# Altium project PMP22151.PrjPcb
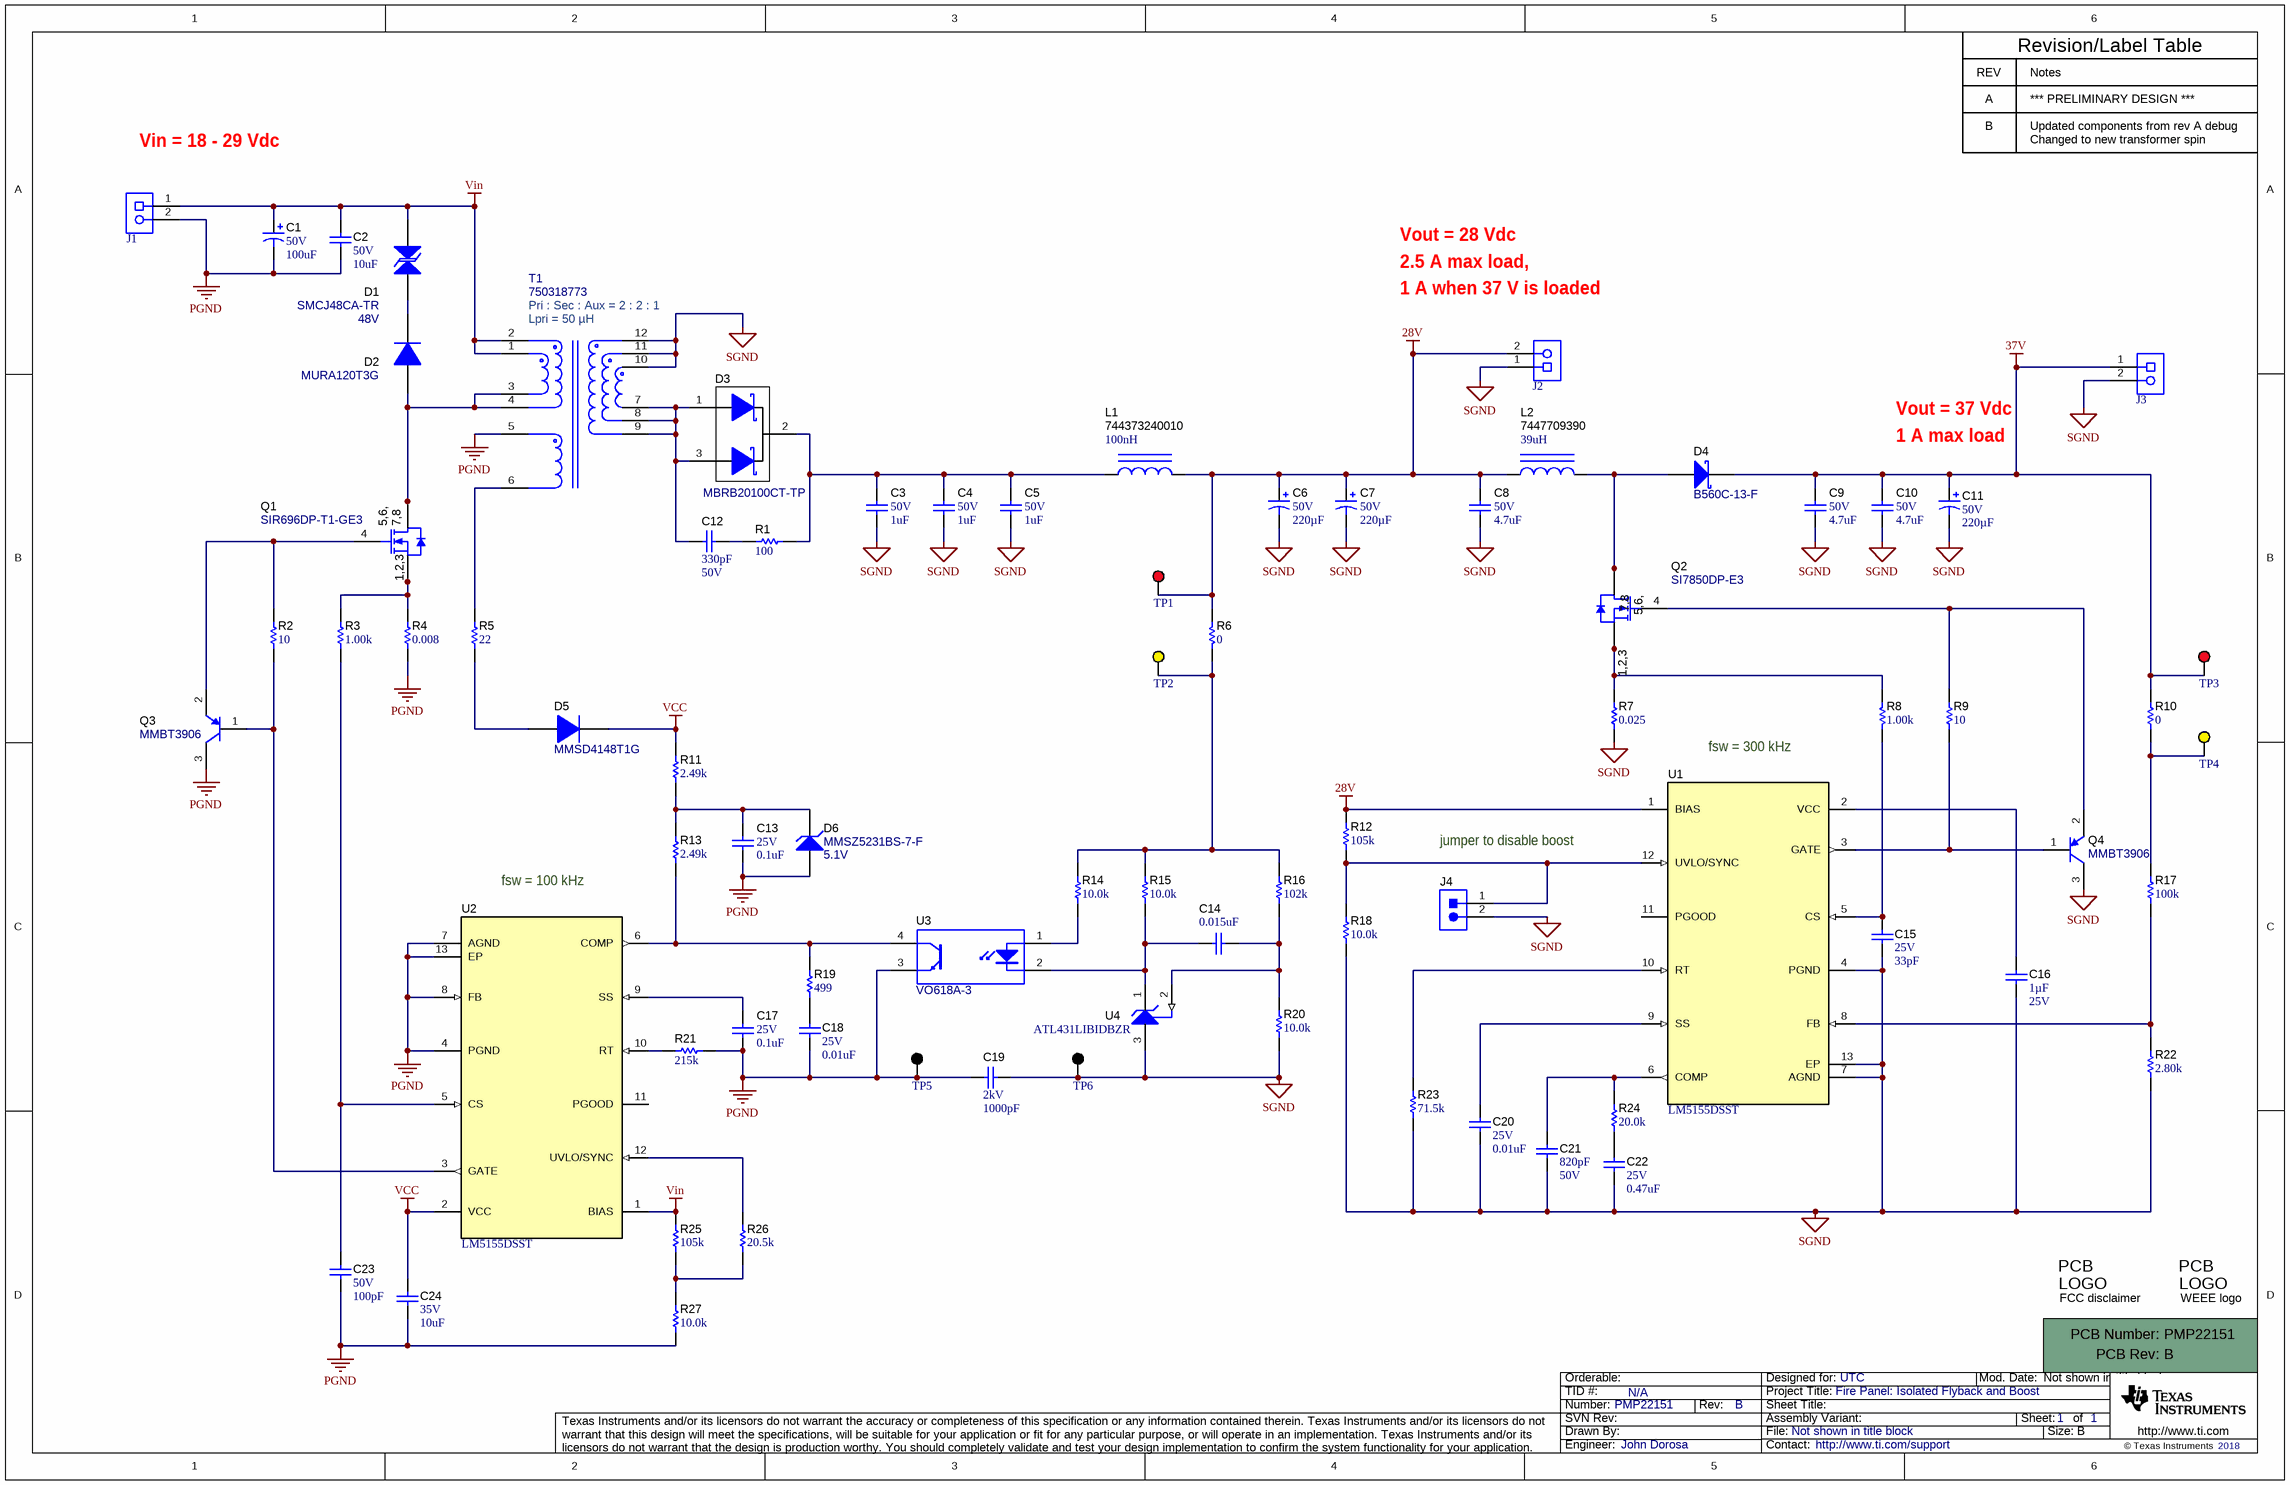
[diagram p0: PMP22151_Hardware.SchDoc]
TID: N/A; TechSupport: http://www.ti.com/support; SCH_Rev: B; PRJ_Title: Fire Panel: Isolated Flyback and Boost; PRJ_Number: PMP22151; PRJ_Engineer: John Dorosa; PRJ_Customer: UTC; PCB_Rev: B; PCB_Layout: John Dorosa; CopyrightYear: 2018
1 sheet, 81 parts. Net scope: global (net labels, ports and power ports of the same name join across sheets).
Board file: PMP22151_PCB.PcbDoc

## Sheet PMP22151_Hardware.SchDoc
size 431 x 279 mm; Date: Not shown in title block; ApprovedBy: Not shown in title block; CheckedBy: Not shown in title block; Author: Not shown in title block; CompanyName: Not shown in title block; Engineer: Not shown in title block; Organization: Not shown in title block; Address1: Not shown in title block; Address2: Not shown in title block; Address3: Not shown in title block; Address4: Not shown in title block; DocumentNumber: 1; Revision: Use project parameter SCH_Rev; SheetNumber: 1; SheetTotal: 1; PageSetup: Record=PageOptions¦CenterHorizontal=True¦CenterVertical=True¦PrintScale=1.00¦XCorrection=1.00¦YCorrection=1.00¦PrintKind=0¦BorderSize=5000000¦LeftOffset=0¦BottomOffset=0¦Orientation=2¦PaperLength=1000¦PaperWidth=1000¦Scale=100¦PaperSource=15¦PrintQuality=600¦MediaType=1¦DitherType=10¦PaperKind=Letter¦PrintScaleMode=1

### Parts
!PCB1  Printed Circuit Board  (value not drawn)  (mechanical)
C1  VDC_V: 50V  ValueDisplayed: 100uF  [ZLJ_800X1150]  (hidden comment: 50ZLJ100MT78X11.5)
C2  VDC_V: 50V  ValueDisplayed: 10uF  [1206_180]  (hidden comment: GRM31CR61H106KA12L)
C3  VDC_V: 50V  ValueDisplayed: 1uF  [1206]  (hidden comment: GRM31MR71H105KA88L)
C4  VDC_V: 50V  ValueDisplayed: 1uF  [1206]  (hidden comment: GRM31MR71H105KA88L)
C5  VDC_V: 50V  ValueDisplayed: 1uF  [1206]  (hidden comment: GRM31MR71H105KA88L)
C6  VDC_V: 50V  ValueDisplayed: 220µF  [WCAP-ATLI_1000x1600]  (hidden comment: 860080675015)
C7  VDC_V: 50V  ValueDisplayed: 220µF  [WCAP-ATLI_1000x1600]  (hidden comment: 860080675015)
C8  VDC_V: 50V  ValueDisplayed: 4.7uF  [1206_180]  (hidden comment: GRM31CR71H475KA12L)
C9  VDC_V: 50V  ValueDisplayed: 4.7uF  [1206_180]  (hidden comment: GRM31CR71H475KA12L)
C10  VDC_V: 50V  ValueDisplayed: 4.7uF  [1206_180]  (hidden comment: GRM31CR71H475KA12L)
C11  VDC_V: 50V  ValueDisplayed: 220µF  [WCAP-ATLI_1000x1600]  (hidden comment: 860080675015)
C12  Cap_F: 330pF  VDC_V: 50V  [0603]  (hidden comment: GRM188R71H331KA01D)
C13  VDC_V: 25V  ValueDisplayed: 0.1uF  [0603]  (hidden comment: GRM188R71E104KA01D)
C14  ValueDisplayed: 0.015uF  [0603]  (hidden comment: GRM188R71E153KA01D)
C15  VDC_V: 25V  ValueDisplayed: 33pF  [0402]  (hidden comment: GRM1555C1E330JA01D)
C16  Cap_F: 1µF  VDC_V: 25V  [0805_HV]  (hidden comment: GRM219R71E105KA88D)
C17  VDC_V: 25V  ValueDisplayed: 0.1uF  [0603]  (hidden comment: GRM188R71E104KA01D)
C18  VDC_V: 25V  ValueDisplayed: 0.01uF  [0603]  (hidden comment: GRM188R71E103KA01D)
C19  VDC_V: 2kV  ValueDisplayed: 1000pF  [1812_254]  (hidden comment: 1812GC102KA1)
C20  VDC_V: 25V  ValueDisplayed: 0.01uF  [0603]  (hidden comment: GRM188R71E103KA01D)
C21  Cap_F: 820pF  VDC_V: 50V  [0603]  (hidden comment: GRM188R71H821KA01D)
C22  VDC_V: 25V  ValueDisplayed: 0.47uF  [0603]  (hidden comment: GCM188R71E474KA64D)
C23  VDC_V: 50V  ValueDisplayed: 100pF  [0402]  (hidden comment: 885012205055)
C24  VDC_V: 35V  ValueDisplayed: 10uF  [1206_190]  (hidden comment: C3216X7R1V106M160AC)
D1  SMCJ48CA-TR  value 48V  [SMC_Bi]
D2  MURA120T3G  [SMA]
D3  MBRB20100CT-TP  [DDPAK]
D4  B560C-13-F  [SMC]
D5  MMSD4148T1G  [SOD-123]
D6  MMSZ5231BS-7-F  value 5.1V  [SOD-323]
J1  691214110002  [Wurth_691214110002]  (value not drawn)
J2  691214110002  [Wurth_691214110002]  (value not drawn)
J3  691214110002  [Wurth_691214110002]  (value not drawn)
J4  61300211121  [WURTH_61300211121]  (value not drawn)
L1  744373240010  ValueDisplayed: 100nH  [WE-LHMI_4020]
L2  7447709390  ValueDisplayed: 39uH  [WE-PD_1210]
Logo1  FCC disclaimer  [FCC_disclaimer]  (no BOM)
Logo2  WEEE logo  [WEEE_Minimum]  (no BOM)
Q1  SIR696DP-T1-GE3  [PowerPAK_SO-8]
Q2  SI7850DP-E3  [PowerPAK_SO-8]
Q3  MMBT3906  [SOT-23]
Q4  MMBT3906  [SOT-23]
R1  ValueDisplayed: 100  [2512]  (hidden comment: CRCW2512100RJNEG)
R2  ValueDisplayed: 10  [0603]  (hidden comment: CRCW060310R0JNEA)
R3  ValueDisplayed: 1.00k  [0603]  (hidden comment: CRCW06031K00FKEA)
R4  ValueDisplayed: 0.008  [2512]  (hidden comment: ERJ-M1WSF8M0U)
R5  ValueDisplayed: 22  [0603]  (hidden comment: CRCW060322R0JNEA)
R6  ValueDisplayed: 0  [0603]  (hidden comment: CRCW06030000Z0EA)
R7  ValueDisplayed: 0.025  [2010]  (hidden comment: CSRN2010FK25L0)
R8  ValueDisplayed: 1.00k  [0603]  (hidden comment: CRCW06031K00FKEA)
R9  ValueDisplayed: 10  [0603]  (hidden comment: CRCW060310R0JNEA)
R10  ValueDisplayed: 0  [0603]  (hidden comment: CRCW06030000Z0EA)
R11  ValueDisplayed: 2.49k  [0603]  (hidden comment: CRCW06032K49FKEA)
R12  ValueDisplayed: 105k  [0603]  (hidden comment: CRCW0603105KFKEA)
R13  ValueDisplayed: 2.49k  [0603]  (hidden comment: CRCW06032K49FKEA)
R14  ValueDisplayed: 10.0k  [0603]  (hidden comment: CRCW060310K0FKEA)
R15  ValueDisplayed: 10.0k  [0603]  (hidden comment: CRCW060310K0FKEA)
R16  ValueDisplayed: 102k  [0603]  (hidden comment: CRCW0603102KFKEA)
R17  ValueDisplayed: 100k  [0603]  (hidden comment: CRCW0603100KFKEA)
R18  ValueDisplayed: 10.0k  [0603]  (hidden comment: CRCW060310K0FKEA)
R19  ValueDisplayed: 499  [0603]  (hidden comment: CRCW0603499RFKEA)
R20  ValueDisplayed: 10.0k  [0603]  (hidden comment: CRCW060310K0FKEA)
R21  ValueDisplayed: 215k  [0603]  (hidden comment: CRCW0603215KFKEA)
R22  ValueDisplayed: 2.80k  [0603]  (hidden comment: CRCW06032K80FKEA)
R23  ValueDisplayed: 71.5k  [0603]  (hidden comment: CRCW060371K5FKEA)
R24  ValueDisplayed: 20.0k  [0603]  (hidden comment: CRCW060320K0FKEA)
R25  ValueDisplayed: 105k  [0603]  (hidden comment: CRCW0603105KFKEA)
R26  ValueDisplayed: 20.5k  [0603]  (hidden comment: CRCW060320K5FKEA)
R27  ValueDisplayed: 10.0k  [0603]  (hidden comment: CRCW060310K0FKEA)
T1  750318773  [FP-750318773_PTH_32MM0_33MM0-MFG]
TP1  5000  [Keystone5000]  (value not drawn)
TP2  5004  [Keystone5004]  (value not drawn)
TP3  5000  [Keystone5000]  (value not drawn)
TP4  5004  [Keystone5004]  (value not drawn)
TP5  5011  [Keystone5011]  (value not drawn)
TP6  5011  [Keystone5011]  (value not drawn)
U1  LM5155DSST  [DSS0012B]
U2  LM5155DSST  [DSS0012B]
U3  VO618A-3  [DIP-4]
U4  ATL431LIBIDBZR  [DBZ0003A_N]

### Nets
28V: C6.1(+) C7.1(+) C8.1 J2.2 L1.2 L2.1 R6.2 R12.2 TP1.1 U1.1(BIAS)
37V: C9.1 C10.1 C11.1(+) D4.1(K) J3.1 R10.2 TP3.1
PGND: C1.2(-) C2.2 C13.1 C17.1 C18.1 C19.2 C23.2 C24.2 D6.2(A) J1.2 Q3.3(C) R4.1 R21.2 R27.1 T1.5 TP5.1 U2.4(PGND) U2.7(AGND) U2.8(FB) U2.13(EP) U3.3(E)
SGND: C3.2 C4.2 C5.2 C6.2(-) C7.2(-) C8.2 C9.2 C10.2 C11.2(-) C15.2 C16.2 C19.1 C20.2 C21.2 C22.2 J2.1 J3.2 J4.2 Q4.3(C) R7.1 R18.1 R20.1 R22.1 R23.1 T1.10 T1.11 T1.12 TP6.1 U1.4(PGND) U1.7(AGND) U1.13(EP) U4.3(ANODE)
VCC: C24.1 D5.1(K) R11.2 U2.2(VCC)
Vin: C1.1(+) C2.1 D1.1 J1.1 R25.2 T1.1 T1.2 U2.1(BIAS)
NetC3_1: C3.1 C4.1 C5.1 D3.2(K) L1.1 R1.2
NetC12_1: C12.1 R1.1
NetC12_2: C12.2 D3.1(A) D3.3(A) T1.7 T1.8 T1.9
NetC13_2: C13.2 D6.1(K) R11.1 R13.2
NetC14_1: C14.1 R16.1 R20.2 U4.2(REF)
NetC14_2: C14.2 R15.1 U3.2(K) U4.1(CATHODE)
NetC15_1: C15.1 R8.1 U1.5(CS)
NetC16_1: C16.1 U1.2(VCC)
NetC17_2: C17.2 U2.9(SS)
NetC18_2: C18.2 R19.1
NetC20_1: C20.1 U1.9(SS)
NetC21_1: C21.1 R24.2 U1.6(COMP)
NetC22_1: C22.1 R24.1
NetC23_1: C23.1 R3.1 U2.5(CS)
NetD1_2: D1.2 D2.1(K)
NetD2_2: D2.2(A) Q1.5(D) Q1.6(D) Q1.7(D) Q1.8(D) Q1.9(D) T1.3 T1.4
NetD4_2: D4.2(A) L2.2 Q2.5(D) Q2.6(D) Q2.7(D) Q2.8(D) Q2.9(D)
NetD5_2: D5.2(A) R5.1
NetJ4_1: J4.1 R12.1 R18.2 U1.12(UVLO/SYNC)
NetQ1_1: Q1.1(S) Q1.2(S) Q1.3(S) R3.2 R4.2
NetQ1_4: Q1.4(G) Q3.2(E) R2.2
NetQ2_1: Q2.1(S) Q2.2(S) Q2.3(S) R7.2 R8.2
NetQ2_4: Q2.4(G) Q4.2(E) R9.2
NetQ3_1: Q3.1(B) R2.1 U2.3(GATE)
NetQ4_1: Q4.1(B) R9.1 U1.3(GATE)
NetR5_2: R5.2 T1.6
NetR6_1: R6.1 R14.2 R15.2 R16.2 TP2.1
NetR10_1: R10.1 R17.2 TP4.1
NetR13_1: R13.1 R19.2 U2.6(COMP) U3.4(C)
NetR14_1: R14.1 U3.1(A)
NetR17_1: R17.1 R22.2 U1.8(FB)
NetR21_1: R21.1 U2.10(RT)
NetR23_2: R23.2 U1.10(RT)
NetR25_1: R25.1 R26.1 R27.2
NetR26_2: R26.2 U2.12(UVLO/SYNC)

Not connected (* = marked no-connect by the designer): U1 11(PGOOD); U2 11(PGOOD)

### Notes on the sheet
- REV
- A
- Notes
- *** PRELIMINARY DESIGN ***
- Revision/Label Table
- Vin = 18 - 29 Vdc
- B
- Updated components from rev A debug
- Changed to new transformer spin
- Vout = 28 Vdc
- 2.5 A max load,
- 1 A when 37 V is loaded
- (near T1) Pri : Sec : Aux = 2 : 2 : 1
- (near T1) Lpri = 50 µH
- Vout = 37 Vdc
- 1 A max load
- fsw = 300 kHz
- fsw = 100 kHz
- jumper to disable boost

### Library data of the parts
!PCB1 = CMP-0003618-2: Manufacturer: Any; PartNumber: PMP22151
C1 = CMP-0009787-2: CAP, AL, 100 uF, 50 V, +/- 20%, 0.12 ohm, TH; Manufacturer: Rubycon; TaMin_C: -40°C; ESR_ohm: 0.12; Polarized: Y; SizeAreaWB_mm2: 100; U/M: EA; Value: 100uF; TaMax_C: 105°C; SizeZ_mm: 13; SizeX_mm: 8; Cap_Case: 8x11.5; SizeArea_mm2: 64; CompType: Capacitor; AEC Qualified: N; Cap_F: 100µF; IRMS_A: 950mA; AEC Category: Q200
C2 = CMP-0008954-2: CAP, CERM, 10 uF, 50 V, +/- 10%, X5R, 1206; Manufacturer: MuRata; TaMin_C: -55°C; Polarized: N; SizeAreaWB_mm2: 10.92; Value1: Unknown; U/M: EA; Value: 10uF; TaMax_C: 85°C; SizeZ_mm: 1.8; SizeX_mm: 3.2; SizeY_mm: 1.6; Cap_Case: 1206; SizeArea_mm2: 5.12; Cap_F: 10µF; AEC Category: Q200
C3-C5 = CMP-0008992-2: CAP, CERM, 1 uF, 50 V, +/- 10%, X7R, 1206; Manufacturer: MuRata; TaMin_C: -55°C; Polarized: N; SizeAreaWB_mm2: 10.92; Value1: Unknown; U/M: EA; Value: 1uF; TaMax_C: 125°C; SizeZ_mm: 1.35; SizeX_mm: 3.2; SizeY_mm: 1.6; SizeArea_mm2: 5.12; Cap_F: 1µF; AEC Category: Q200
C6 C7 C11 = CMP-0081643-1: CAP, AL, 220 µF, 50 V, +/- 20%, TH; Manufacturer: Wurth Elektronik; IRMS_A: 1.385A; SizeAreaWB_mm2: 144; SizeArea_mm2: 100; AEC Qualified: N; AEC Category: Q200; Value: 220uF; TaMax_C: 105°C; SizeZ_mm: 17.5; Polarized: Y; TaMin_C: -55°C; SizeY_mm: 10; U/M: EA; CompType: Capacitor; Cap_Case: 10x16mm
C8-C10 = CMP-0008969-2: CAP, CERM, 4.7 uF, 50 V, +/- 10%, X7R, 1206; Manufacturer: MuRata; TaMin_C: -55°C; Polarized: N; SizeAreaWB_mm2: 10.92; Value1: Unknown; U/M: EA; Value: 4.7uF; TaMax_C: 125°C; SizeZ_mm: 1.8; SizeX_mm: 3.2; SizeY_mm: 1.6; Cap_Case: 2220; SizeArea_mm2: 5.12; Cap_F: 4.7µF; AEC Category: Q200
C12 = CMP-0007449-4: CAP, CERM, 330 pF, 50 V, +/- 10%, X7R, 0603; Manufacturer: MuRata; TaMin_C: -55°C; Polarized: N; SizeAreaWB_mm2: 4.68; Value1: Unknown; U/M: EA; Value: 330pF; TaMax_C: 125°C; SizeZ_mm: 1; SizeX_mm: 1.6; SizeY_mm: 0.8; SizeArea_mm2: 1.28; AEC Category: Q200
C13 C17 = CMP-0007404-4: CAP, CERM, 0.1 uF, 25 V, +/- 10%, X7R, 0603; Manufacturer: MuRata; TaMin_C: -55°C; Polarized: N; SizeAreaWB_mm2: 4.68; Value1: Unknown; U/M: EA; Value: 0.1uF; TaMax_C: 125°C; SizeZ_mm: 1; SizeX_mm: 1.6; SizeY_mm: 0.8; SizeArea_mm2: 1.28; Cap_F: 100nF; AEC Category: Q200
C14 = CMP-0007410-5: CAP, CERM, 0.015 uF, 25 V, +/- 10%, X7R, 0603; Manufacturer: MuRata; TaMin_C: -55°C; Polarized: N; SizeAreaWB_mm2: 4.68; Value1: Unknown; U/M: EA; TaMax_C: 125°C; SizeZ_mm: 1; SizeX_mm: 1.6; SizeY_mm: 0.8; Value2: 25V; SizeArea_mm2: 1.28; Cap_F: 15nF; AEC Category: Q200
C15 = CMP-0006377-2: CAP, CERM, 33 pF, 25 V, +/- 5%, C0G/NP0, 0402; Manufacturer: MuRata; TaMin_C: -55°C; Polarized: N; SizeAreaWB_mm2: 3; Value1: Unknown; U/M: EA; Value: 33pF; TaMax_C: 125°C; SizeZ_mm: 0.6; SizeX_mm: 1; SizeY_mm: 0.5; AEC Category: Q200
C16 = CMP-0008217-2: CAP, CERM, 1 uF, 25 V, +/- 10%, X7R, 0805; Manufacturer: MuRata; TaMin_C: -55°C; Polarized: N; SizeAreaWB_mm2: 6.75; Value1: Unknown; U/M: EA; Value: 1uF; TaMax_C: 125°C; SizeZ_mm: 1.45; SizeX_mm: 2; SizeY_mm: 1.25; Cap_Case: 0805; SizeArea_mm2: 2.5; AEC Category: Q200
C18 C20 = CMP-0007403-4: CAP, CERM, 0.01 uF, 25 V, +/- 10%, X7R, 0603; Manufacturer: MuRata; TaMin_C: -55°C; Polarized: N; SizeAreaWB_mm2: 4.68; Value1: Unknown; U/M: EA; Value: 0.01uF; TaMax_C: 125°C; SizeZ_mm: 1; SizeX_mm: 1.6; SizeY_mm: 0.8; SizeArea_mm2: 1.28; Cap_F: 10nF; AEC Category: Q200
C19 = CMP-0009293-2: CAP, CERM, 1000 pF, 2000 V, +/- 10%, X7R, 1812; Manufacturer: AVX; TaMin_C: -55°C; Polarized: N; SizeAreaWB_mm2: 23.1; Value1: Unknown; U/M: EA; Value: 1000pF; TaMax_C: 125°C; SizeZ_mm: 2.54; SizeX_mm: 4.5; SizeY_mm: 3.2; Cap_Case: 1812; Value2: 2000V; SizeArea_mm2: 14.4; Cap_F: 1nF; AEC Category: Q200
C21 = CMP-0007464-4: CAP, CERM, 820 pF, 50 V, +/- 10%, X7R, 0603; Manufacturer: MuRata; TaMin_C: -55°C; Polarized: N; SizeAreaWB_mm2: 4.68; Value1: Unknown; U/M: EA; Value: 820pF; TaMax_C: 125°C; SizeZ_mm: 1; SizeX_mm: 1.6; SizeY_mm: 0.8; SizeArea_mm2: 1.28; AEC Category: Q200
C22 = CMP-0007142-4: CAP, CERM, 0.47 uF, 25 V, +/- 10%, X7R, AEC-Q200 Grade 1, 0603; Manufacturer: MuRata; TaMin_C: -55°C; Polarized: N; SizeAreaWB_mm2: 4.68; Value1: Unknown; U/M: EA; Value: 0.47uF; TaMax_C: 125°C; SizeZ_mm: 1; SizeX_mm: 1.6; SizeY_mm: 0.8; SizeArea_mm2: 1.28; AEC Qualified: Y; Cap_F: 470nF; AEC Category: Q200
C23 = CMP-0006230-2: CAP, CERM, 100 pF, 50 V, +/- 10%, X7R, 0402; Manufacturer: Wurth Elektronik; TaMin_C: -55°C; Polarized: N; SizeAreaWB_mm2: 3; Value1: Unknown; U/M: EA; Value: 100pF; TaMax_C: 125°C; SizeZ_mm: 0.6; SizeX_mm: 1; SizeY_mm: 0.5; AEC Category: Q200
C24 = CMP-0008706-2: CAP, CERM, 10 uF, 35 V, +/- 20%, X7R, 1206_190; Manufacturer: TDK; TaMin_C: -55°C; Polarized: N; SizeAreaWB_mm2: 10.92; Value1: Unknown; U/M: EA; Value: 10uF; TaMax_C: 125°C; SizeZ_mm: 1.9; SizeX_mm: 3.2; SizeY_mm: 1.6; Cap_Case: 1206; SizeArea_mm2: 5.12; Cap_F: 10µF; AEC Category: Q200
D1 = CMP-0085460-1: Diode, TVS, Bi, 48 V, 77.4 Vc, 1500 W, 20 A, SMC (No Polarity Mark); Manufacturer: STMicroelectronics; AEC Category: Q101; Ipp: 20A; Vc: 77.4V; RJA_CperW: 90; SizeX_mm: 7.94; SizeY_mm: 5.9; SizeArea_mm2: 46.846; SizeAreaWB_mm2: 78.526; Ppk: 1.5kW; AEC Qualified: N; Vbr_Min: 53.3V; SizeZ_mm: 2.62
D2 = CMP-0029038-2: Diode, Ultrafast, 200 V, 1 A, SMA; Manufacturer: ON Semiconductor; Value: 200V; Value1: 1A; Value2: 0.0875V; Vf_V: 87.5mV; SizeY_mm: 2.92; Green_REACh: Passed; SizeX_mm: 5.59; Green_Lifecycle: Active; TJmax_C: 175°C; SizeArea_mm2: 16.3228; SizeAreaWB_mm2: 37.3428; SizeZ_mm: 2.87; AEC Category: Q101
D3 = CMP-0076915-3: Diode, Schottky, 100 V, 20 A, DDPAK; Manufacturer: Micro Commercial Components; Value: 100V; RJC_CperW: 2.0; Io_A: 20A; SizeY_mm: 10.16; Green_REACh: Incomplete; TJmax_C: 150°C; AEC Category: Q101; Vf_V: 850mV; SizeZ_mm: 4.445; Green_Lifecycle: Not Set; SizeX_mm: 15.245; SizeAreaWB_mm2: 209.6992; Value2: 0.85V; SizeArea_mm2: 154.8892
D4 = CMP-0028433-2: Diode, Schottky, 60 V, 5 A, SMC; Manufacturer: Diodes Inc.; Vf_V: 700mV; AEC Category: Q101; Vr_V: 60V; Value1: 5A; RJC_CperW: 10; Value2: 0.7V; Value: 60V; SizeX_mm: 8.13; TJmax_C: 125°C; SizeArea_mm2: 50.5686; Green_REACh: Passed; Green_Lifecycle: Active; SizeAreaWB_mm2: 83.2686; SizeY_mm: 6.22; SizeZ_mm: 2.6
D5 = CMP-0029032-2: Diode, Switching, 100 V, 0.2 A, SOD-123; Manufacturer: ON Semiconductor; Value: 100V; SizeY_mm: 1.7; Io_A: 200mA; SizeAreaWB_mm2: 13.095; SizeArea_mm2: 6.545; Vf_V: 1V; TJmax_C: 150°C; SizeX_mm: 3.85; SizeZ_mm: 1.35; Value1: 0.2A; Green_Lifecycle: Active; AEC Category: Q101; Green_REACh: Passed
D6 = CMP-0005854-3: Diode, Zener, 5.1 V, 200 mW, SOD-323; Manufacturer: Diodes Inc.; SizeX_mm: 2.7; SizeZ_mm: 1; RJA_CperW: 350; Power_W: 200mW; SizeAreaWB_mm2: 8.695; AEC Category: Q101; Value1: 0.2W; SizeArea_mm2: 3.645; SizeY_mm: 1.35
J1-J3 = CMP-0054825-2: Terminal Block, 3.5mm, 2x1, Tin, TH; Manufacturer: Wurth Elektronik; Pitch_mm: 3.5; CT: TRUE; CNHeader: FALSE; Voltage_V: 300V; Gender: Female; Cert_UL: Y; Row_Count: 1; Current_A: 10A
J4 = CMP-0054794-1: Header, 2.54 mm, 2x1, Gold, TH; Manufacturer: Wurth Elektronik; CNHeader: TRUE; Green_Lifecycle: Active; Green_REACh: Passed; CT: FALSE
L1 = CMP-0064065-1: Inductor, Shielded Drum Core, Powdered Iron, 100 nH, 12 A, 0.0032 ohm, SMD; Manufacturer: Wurth Elektronik; Isat: 30A @ 20% inductance drop; Irms: 12A @ 40C rise; Green_Lifecycle: Active; SizeAreaWB_mm2: 27.577; DCR_ohm: 3.2m; Green_REACh: Passed; Value: 100nH; Imax_A: 12A; SizeZ_mm: 2; SizeX_mm: 4.45; SizeY_mm: 4.06; SizeArea_mm2: 18.067; AEC Category: Q200
L2 = CMP-0064541-2: Inductor, Shielded Drum Core, Metal Composite, 39 uH, 4.1 A, 0.0439 ohm, SMD; Manufacturer: Wurth Elektronik; Isat: 5A @ 10% inductance drop; Irms: 4.1A @ 40C rise; Green_Lifecycle: Active; SizeAreaWB_mm2: 196; DCR_ohm: 0.0439; Green_REACh: Passed; Value: 39uH; Imax_A: 4.1A; SizeZ_mm: 10; SizeX_mm: 12; SizeArea_mm2: 144; Ind_H: 39µH; AEC Category: Q200
Logo1 = CMP-0074847-1: FCC_disclaimer; Library Reference: Logo
Logo2 = CMP-0074769-1
Q1 = CMP-0086346-1: MOSFET, N-CH, 150V, 60 A, PowerPAK SO-8; Alternate Manufacturer: None; Manufacturer: Vishay-Siliconix; AEC Category: Q101; Value2: ? nC; VdsMax_V: 200V; SizeY_mm: 4.9; SizeZ_mm: 1.12; Value1: ? ohm; SizeAreaWB_mm2: 55.131; ChMode: Enhancement; IdsMax_A: 60A; AEC Qualified: N; SizeArea_mm2: 29.351; SizeX_mm: 5.99; Vgs_V: 20V; Value: 200V
Q2 = CMP-0000869-1: MOSFET, N-CH, 60 V, 6.2 A, PowerPAK SO-8; Alternate Manufacturer: None; Manufacturer: Vishay-Siliconix; SizeZ_mm: 1.12; ChType: N; Value2: 18 nC; Value1: 0.02; VdsMax_V: 60V; SizeX_mm: 5.99; SizeY_mm: 4.9; Vgs_V: 20V; Value: 60V; Rdson45_ohm: 0.025; SizeArea_mm2: 29.351; AEC Category: Q101; IdsMax_A: 6.2A; SizeAreaWB_mm2: 55.131; U/M: EA; QgTyp_nC: 18
Q3 Q4 = CMP-0000325-1: Transistor, PNP, 40 V, 0.2 A, SOT-23; Manufacturer: Fairchild Semiconductor; TaMax_C: 150°C; Value2: 300; Value1: 0.2 A; Vcesat1_V: 250mV; SizeX_mm: 2.5; SizeY_mm: 3; TaMin_C: -55°C; IcRated_A: 200mA; CompType: BJT; SizeZ_mm: 1.1; Value: 40 V; SizeArea_mm2: 7.5; NPN: 0; Vceo_V: 40V; PNP: 1; AEC Category: Q101; SizeAreaWB_mm2: 14; U/M: EA
R1 = CMP-0015867-3: RES, 100, 5%, 1 W, AEC-Q200 Grade 0, 2512; Manufacturer: Vishay-Dale; Power_W: 1W; TempCo: 200 ppm/C; Value_Code: 100R; Value: 100; EIA_Code: E24; SizeX_mm: 6.3; SizeY_mm: 3.2; SizeZ_mm: 0.71; SizeArea_mm2: 20.16; AEC Qualified: Y; VDC_V: 500V; AEC Grade: 0; AEC Category: Q200
R2 R9 = CMP-0025703-4: RES, 10, 5%, 0.1 W, AEC-Q200 Grade 0, 0603; Manufacturer: Vishay-Dale; Power_W: 100mW; TempCo: 200 ppm/C; Value_Code: 10R0; Value: 10; EIA_Code: E24; SizeX_mm: 1.6; SizeY_mm: 0.8; SizeZ_mm: 1; Value2: 0.1W; SizeArea_mm2: 1.28; AEC Qualified: Y; VDC_V: 75V; AEC Category: Q200; AEC Grade: 0
R3 R8 = CMP-0022109-5: RES, 1.00 k, 1%, 0.1 W, AEC-Q200 Grade 0, 0603; Manufacturer: Vishay-Dale; Power_W: 100mW; TempCo: 100 ppm/C; Value_Code: 1k00; Value: 1.00k; EIA_Code: E96; Res_ohm: 1k; SizeX_mm: 1.6; SizeY_mm: 0.8; SizeZ_mm: 1; Value2: 0.1W; SizeArea_mm2: 1.28; AEC Qualified: Y; VDC_V: 75V; AEC Category: Q200; AEC Grade: 0
R4 = CMP-0015816-2: RES, 0.008, 1%, 1 W, 2512; Manufacturer: Panasonic; Power_W: 1W; TempCo: 100 ppm/C; Value_Code: 8L000; U/M: EA; Value: 0.008; EIA_Code: E96; Res_ohm: 8m; SizeX_mm: 6.3; SizeY_mm: 3.2; SizeZ_mm: 0.71; SizeArea_mm2: 20.16; AEC Category: Q200
R5 = CMP-0025758-4: RES, 22, 5%, 0.1 W, AEC-Q200 Grade 0, 0603; Manufacturer: Vishay-Dale; Power_W: 100mW; TempCo: 200 ppm/C; Value_Code: 22R0; Value: 22; EIA_Code: E24; SizeX_mm: 1.6; SizeY_mm: 0.8; SizeZ_mm: 1; Value2: 0.1W; SizeArea_mm2: 1.28; AEC Qualified: Y; VDC_V: 75V; AEC Category: Q200; AEC Grade: 0
R6 R10 = CMP-0025697-4: RES, 0, 5%, 0.1 W, AEC-Q200 Grade 0, 0603; Manufacturer: Vishay-Dale; Power_W: 100mW; TempCo: 200 ppm/C; Value_Code: 0000; Value: 0; EIA_Code: E24; SizeX_mm: 1.6; SizeY_mm: 0.8; SizeZ_mm: 1; Value2: 0.1W; SizeArea_mm2: 1.28; AEC Qualified: Y; VDC_V: 75V; AEC Category: Q200
R7 = CMP-0016517-2: RES, 0.025, 1%, 1 W, 2010; Manufacturer: Stackpole Electronics Inc; Power_W: 1W; TempCo: 250 ppm/C; Value_Code: R025; U/M: EA; Value: 0.025; EIA_Code: E96; SizeX_mm: 5; SizeY_mm: 2.5; SizeZ_mm: 1.66; SizeArea_mm2: 12.5; AEC Category: Q200
R11 R13 = CMP-0022277-4: RES, 2.49 k, 1%, 0.1 W, AEC-Q200 Grade 0, 0603; Manufacturer: Vishay-Dale; Power_W: 100mW; TempCo: 100 ppm/C; Value_Code: 2k49; Value: 2.49k; EIA_Code: E96; SizeX_mm: 1.6; SizeY_mm: 0.8; SizeZ_mm: 1; Value2: 0.1W; SizeArea_mm2: 1.28; AEC Qualified: Y; VDC_V: 75V; AEC Category: Q200; AEC Grade: 0
R12 R25 = CMP-0021994-4: RES, 105 k, 1%, 0.1 W, AEC-Q200 Grade 0, 0603; Manufacturer: Vishay-Dale; Power_W: 100mW; TempCo: 100 ppm/C; Value: 105k; EIA_Code: E96; SizeX_mm: 1.6; SizeY_mm: 0.8; SizeZ_mm: 1; Value2: 0.1W; SizeArea_mm2: 1.28; AEC Qualified: Y; VDC_V: 75V; AEC Category: Q200; AEC Grade: 0
R14 R15 R18 R20 R27 = CMP-0021998-4: RES, 10.0 k, 1%, 0.1 W, AEC-Q200 Grade 0, 0603; Manufacturer: Vishay-Dale; Power_W: 100mW; TempCo: 100 ppm/C; Value_Code: 10k0; Value: 10.0k; EIA_Code: E96; Res_ohm: 10k; SizeX_mm: 1.6; SizeY_mm: 0.8; SizeZ_mm: 1; Value2: 0.1W; SizeArea_mm2: 1.28; AEC Qualified: Y; VDC_V: 75V; AEC Category: Q200; AEC Grade: 0
R16 = CMP-0021992-4: RES, 102 k, 1%, 0.1 W, AEC-Q200 Grade 0, 0603; Manufacturer: Vishay-Dale; Power_W: 100mW; TempCo: 100 ppm/C; Value: 102k; EIA_Code: E96; SizeX_mm: 1.6; SizeY_mm: 0.8; SizeZ_mm: 1; Value2: 0.1W; SizeArea_mm2: 1.28; AEC Qualified: Y; VDC_V: 75V; AEC Category: Q200; AEC Grade: 0
R17 = CMP-0021990-4: RES, 100 k, 1%, 0.1 W, AEC-Q200 Grade 0, 0603; Manufacturer: Vishay-Dale; Power_W: 100mW; TempCo: 100 ppm/C; Value: 100k; EIA_Code: E96; SizeX_mm: 1.6; SizeY_mm: 0.8; SizeZ_mm: 1; Value2: 0.1W; SizeArea_mm2: 1.28; AEC Qualified: Y; VDC_V: 75V; AEC Category: Q200; AEC Grade: 0
R19 = CMP-0022446-5: RES, 499, 1%, 0.1 W, AEC-Q200 Grade 0, 0603; Manufacturer: Vishay-Dale; Power_W: 100mW; TempCo: 100 ppm/C; Value_Code: 499R; Value: 499; EIA_Code: E96; SizeX_mm: 1.6; SizeY_mm: 0.8; SizeZ_mm: 1; Value2: 0.1W; SizeArea_mm2: 1.28; AEC Qualified: Y; VDC_V: 75V; AEC Category: Q200; AEC Grade: 0
R21 = CMP-0022210-4: RES, 215 k, 1%, 0.1 W, AEC-Q200 Grade 0, 0603; Manufacturer: Vishay-Dale; Power_W: 100mW; TempCo: 100 ppm/C; Value: 215k; EIA_Code: E96; SizeX_mm: 1.6; SizeY_mm: 0.8; SizeZ_mm: 1; Value2: 0.1W; SizeArea_mm2: 1.28; AEC Qualified: Y; VDC_V: 75V; AEC Category: Q200; AEC Grade: 0
R22 = CMP-0022282-4: RES, 2.80 k, 1%, 0.1 W, AEC-Q200 Grade 0, 0603; Manufacturer: Vishay-Dale; Power_W: 100mW; TempCo: 100 ppm/C; Value_Code: 2k80; Value: 2.80k; EIA_Code: E96; Res_ohm: 2.8k; SizeX_mm: 1.6; SizeY_mm: 0.8; SizeZ_mm: 1; Value2: 0.1W; SizeArea_mm2: 1.28; AEC Qualified: Y; VDC_V: 75V; AEC Category: Q200; AEC Grade: 0
R23 = CMP-0022581-4: RES, 71.5 k, 1%, 0.1 W, AEC-Q200 Grade 0, 0603; Manufacturer: Vishay-Dale; Power_W: 100mW; TempCo: 100 ppm/C; Value_Code: 71k5; Value: 71.5k; EIA_Code: E96; SizeX_mm: 1.6; SizeY_mm: 0.8; SizeZ_mm: 1; Value2: 0.1W; SizeArea_mm2: 1.28; AEC Qualified: Y; VDC_V: 75V; AEC Category: Q200; AEC Grade: 0
R24 = CMP-0022204-4: RES, 20.0 k, 1%, 0.1 W, AEC-Q200 Grade 0, 0603; Manufacturer: Vishay-Dale; Power_W: 100mW; TempCo: 100 ppm/C; Value_Code: 20k0; Value: 20.0k; EIA_Code: E96; Res_ohm: 20k; SizeX_mm: 1.6; SizeY_mm: 0.8; SizeZ_mm: 1; Value2: 0.1W; SizeArea_mm2: 1.28; AEC Qualified: Y; VDC_V: 75V; AEC Category: Q200; AEC Grade: 0
R26 = CMP-0022205-4: RES, 20.5 k, 1%, 0.1 W, AEC-Q200 Grade 0, 0603; Manufacturer: Vishay-Dale; Power_W: 100mW; TempCo: 100 ppm/C; Value_Code: 20k5; Value: 20.5k; EIA_Code: E96; SizeX_mm: 1.6; SizeY_mm: 0.8; SizeZ_mm: 1; Value2: 0.1W; SizeArea_mm2: 1.28; AEC Qualified: Y; VDC_V: 75V; AEC Category: Q200; AEC Grade: 0
T1 = CMP-0087767-1: TRANSFORMER; Manufacturer: Wurth; DCR_ohm: 0.03; Ind_H: 50µH; AEC Qualified: No; Ns1toNp: 1:1/2:1; SizeZ_mm: 14.48mm
TP1 TP3 = CMP-0055137-1: Test Point, Miniature, Red, TH; Manufacturer: Keystone; CNHeader: FALSE; Green_Lifecycle: Active; Green_REACh: Passed; ContactFinish: Silver; CT: TRUE
TP2 TP4 = CMP-0055141-1: Test Point, Miniature, Yellow, TH; Manufacturer: Keystone; CNHeader: FALSE; Green_Lifecycle: Active; Green_REACh: Passed; ContactFinish: Silver; CT: TRUE
TP5 TP6 = CMP-0055148-1: Test Point, Multipurpose, Black, TH; Manufacturer: Keystone; CNHeader: FALSE; Green_Lifecycle: Active; Green_REACh: Passed; ContactFinish: Silver; CT: TRUE
U1 U2 = CMP-0085414-1: 2.2-MHz Wide Input Nonsynchronous Boost, Sepic, Flyback Controller, DSS0012B (WSON-12); Alternate Manufacturer: Texas Instruments; Alternate PartNumber: LM5155DSSR; SizeZ_mm: 0.8; SizeX_mm: 2; CompType: IC; SizeAreaWB_mm2: 12; SizeArea_mm2: 6; AEC Qualified: N; AEC Category: Q200; SizeY_mm: 3
U3 = CMP-0083653-1: Optocoupler, 5.3 kV, 100-200% CTR, SMT; Manufacturer: Vishay-Semiconductor; CTR (Max): 200%; SizeAreaWB_mm2: 71.064; CTR (Min): 100%; SizeZ_mm: 5; SizeX_mm: 8.8; SizeY_mm: 4.58; SizeArea_mm2: 40.304; Voltage_Isolation_Vrms: 5.3kV
U4 = CMP-0084732-1: High Bandwidth Low-Iq Programmable Shunt Regulator, DBZ0003A (SOT-23-3); Manufacturer: Texas Instruments; SizeArea_mm2: 7.5; SizeY_mm: 3; SizeX_mm: 2.5; SizeAreaWB_mm2: 14; AEC Category: Q200; SizeZ_mm: 1.12; AEC Qualified: N; CompType: IC

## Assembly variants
001: not fitted C18 R15 R19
